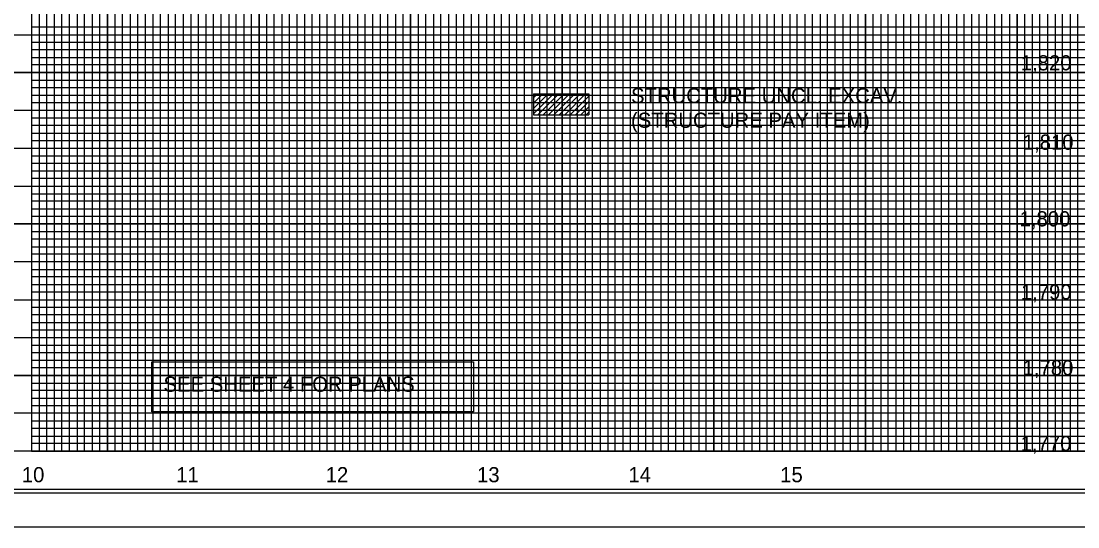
# Model space of a CAD drawing. Extents: x 572269 to 579912, y -56875 to -49627.
# Drawn here: x 573878 to 574575, y -53848 to -53514 of the extents above; entities that cross this region are included whole.
import ezdxf

# ---------------------------------------------------------------- set-up
doc = ezdxf.new("R2010")
doc.units = 0
for name, color, linetype in [('Exist Vertical Profile Horizontal Axis Label Major', 7, 'Continuous'), ('Exist Vertical Profile Vertical Axis Label', 7, 'Continuous'), ('Pattern 9', 7, 'Continuous'), ('Prop Grid Mask', 7, 'Continuous'), ('Prop PFL Text', 7, 'Continuous'), ('Sheet Cutting Line CELL', 7, 'Continuous'), ('Sheet DOT Grid CELL', 7, 'Continuous'), ('Sheet Layout Profile Border', 7, 'Continuous'), ('Sheet Plot Border Inside CELL', 7, 'Continuous'), ('Sheet Plot Border Outside CELL', 7, 'Continuous'), ('Sheet Profile CELL', 7, 'Continuous'), ('Sheet Profile Grid Major CELL', 7, 'Continuous'), ('Sheet Profile Grid Middle CELL', 7, 'Continuous'), ('Sheet Profile Grid Minor CELL', 7, 'Continuous')]:
    doc.layers.add(name, color=color, linetype=linetype)

# ---------------------------------------------------------------- blocks, each defined once
blk = doc.blocks.new('PROFILE SHEET SINGLE')
at = {"layer": 'Sheet Cutting Line CELL'}
blk.add_line((-3.34, -0.5), (30.34, -0.5), dxfattribs=at)
at = {"layer": 'Sheet DOT Grid CELL'}
for p, q in [((1, 21), (1, 0.5)), ((2, 21), (2, 0.5)), ((3, 21), (3, 0.5)), ((4, 21), (4, 0.5)), ((5, 21), (5, 0.5)), ((6, 21), (6, 0.5)), ((7, 21), (7, 0.5)), ((8, 21), (8, 0.5)), ((9, 21), (9, 0.5)), ((10, 21), (10, 0.5)), ((11, 21), (11, 0.5)), ((12, 21), (12, 0.5)), ((13, 21), (13, 0.5)), ((14, 21), (14, 0.5)), ((0, 5.5), (30, 5.5)), ((0, 4.5), (30, 4.5)), ((0, 3.5), (30, 3.5)), ((0, 2.5), (30, 2.5)), ((0, 1.5), (30, 1.5))]:
    blk.add_line(p, q, dxfattribs=at)
at = {"layer": 'Sheet Plot Border Inside CELL'}
blk.add_lwpolyline([(30.25, 21.051), (-3.08, 21.051), (-3.08, -0.051), (30.25, -0.051)], close=True, dxfattribs=at)
at = {"layer": 'Sheet Plot Border Outside CELL'}
blk.add_lwpolyline([(30.34, 21.5), (-3.34, 21.5), (-3.34, -0.5), (30.34, -0.5)], close=True, dxfattribs=at)
at = {"layer": 'Sheet Profile CELL'}
blk.add_line((30, 0.5), (0, 0.5), dxfattribs=at)
blk.add_lwpolyline([(30, 21), (0, 21), (0, 0), (30, 0)], close=True, dxfattribs=at)
at = {"layer": 'Sheet Profile Grid Major CELL'}
for points in [[(1, 21), (1, 0.5), (2, 0.5), (2, 21)], [(3, 21), (3, 0.5), (4, 0.5), (4, 21)], [(5, 21), (5, 0.5), (6, 0.5), (6, 21)], [(7, 21), (7, 0.5), (8, 0.5), (8, 21)], [(9, 21), (9, 0.5), (10, 0.5), (10, 21)], [(11, 21), (11, 0.5), (12, 0.5), (12, 21)], [(13, 21), (13, 0.5), (14, 0.5), (14, 21)], [(30, 5.5), (0, 5.5), (0, 6.5), (30, 6.5)], [(30, 3.5), (0, 3.5), (0, 4.5), (30, 4.5)], [(30, 1.5), (0, 1.5), (0, 2.5), (30, 2.5)]]:
    blk.add_lwpolyline(points, dxfattribs=at)
at = {"layer": 'Sheet Profile Grid Middle CELL'}
for points in [[(1.5, 0.5), (1.5, 21)], [(2.5, 21), (2.5, 0.5), (3.5, 0.5), (3.5, 21)], [(4.5, 21), (4.5, 0.5), (5.5, 0.5), (5.5, 21)], [(6.5, 21), (6.5, 0.5), (7.5, 0.5), (7.5, 21)], [(8.5, 21), (8.5, 0.5), (9.5, 0.5), (9.5, 21)], [(10.5, 21), (10.5, 0.5), (11.5, 0.5), (11.5, 21)], [(12.5, 21), (12.5, 0.5), (13.5, 0.5), (13.5, 21)], [(14.5, 21), (14.5, 0.5), (15.5, 0.5), (15.5, 21)], [(30, 7), (0, 7), (0, 6), (30, 6)], [(30, 5), (0, 5), (0, 4), (30, 4)], [(30, 3), (0, 3), (0, 2), (30, 2)], [(30, 1), (0, 1)]]:
    blk.add_lwpolyline(points, dxfattribs=at)
at = {"layer": 'Sheet Profile Grid Minor CELL'}
for points in [[(1.1, 21), (1.1, 0.5), (1.2, 0.5), (1.2, 21)], [(1.3, 21), (1.3, 0.5), (1.4, 0.5), (1.4, 21)], [(1.6, 21), (1.6, 0.5), (1.7, 0.5), (1.7, 21)], [(1.8, 21), (1.8, 0.5), (1.9, 0.5), (1.9, 21)], [(2.1, 21), (2.1, 0.5), (2.2, 0.5), (2.2, 21)], [(2.3, 21), (2.3, 0.5), (2.4, 0.5), (2.4, 21)], [(2.6, 21), (2.6, 0.5), (2.7, 0.5), (2.7, 21)], [(2.8, 21), (2.8, 0.5), (2.9, 0.5), (2.9, 21)], [(3.1, 21), (3.1, 0.5), (3.2, 0.5), (3.2, 21)], [(3.3, 21), (3.3, 0.5), (3.4, 0.5), (3.4, 21)], [(3.6, 21), (3.6, 0.5), (3.7, 0.5), (3.7, 21)], [(3.8, 21), (3.8, 0.5), (3.9, 0.5), (3.9, 21)], [(4.1, 21), (4.1, 0.5), (4.2, 0.5), (4.2, 21)], [(4.3, 21), (4.3, 0.5)], [(4.3, 0.5), (4.4, 0.5), (4.4, 21)], [(4.6, 21), (4.6, 0.5), (4.7, 0.5), (4.7, 21)], [(4.8, 21), (4.8, 0.5), (4.9, 0.5), (4.9, 21)], [(5.1, 21), (5.1, 0.5), (5.2, 0.5), (5.2, 21)], [(5.3, 21), (5.3, 0.5), (5.4, 0.5), (5.4, 21)], [(5.6, 21), (5.6, 0.5), (5.7, 0.5), (5.7, 21)], [(5.8, 21), (5.8, 0.5), (5.9, 0.5), (5.9, 21)], [(6.1, 21), (6.1, 0.5), (6.2, 0.5), (6.2, 21)], [(6.3, 21), (6.3, 0.5), (6.4, 0.5), (6.4, 21)], [(6.6, 21), (6.6, 0.5), (6.7, 0.5), (6.7, 21)], [(6.8, 21), (6.8, 0.5), (6.9, 0.5), (6.9, 21)], [(7.1, 21), (7.1, 0.5), (7.2, 0.5), (7.2, 21)], [(7.3, 21), (7.3, 0.5), (7.4, 0.5), (7.4, 21)], [(7.6, 21), (7.6, 0.5), (7.9, 0.5), (7.9, 21)], [(8.1, 21), (8.1, 0.5), (8.2, 0.5), (8.2, 21)], [(8.3, 21), (8.3, 0.5), (8.4, 0.5), (8.4, 21)], [(8.6, 21), (8.6, 0.5), (8.7, 0.5), (8.7, 21)], [(8.8, 21), (8.8, 0.5), (8.9, 0.5), (8.9, 21)], [(9.1, 21), (9.1, 0.5), (9.2, 0.5), (9.2, 21)], [(9.3, 21), (9.3, 0.5), (9.4, 0.5), (9.4, 21)], [(9.6, 21), (9.6, 0.5), (9.7, 0.5), (9.7, 21)], [(9.8, 21), (9.8, 0.5), (9.9, 0.5), (9.9, 21)], [(10.1, 21), (10.1, 0.5), (10.2, 0.5), (10.2, 21)], [(10.3, 21), (10.3, 0.5), (10.4, 0.5), (10.4, 21)], [(10.6, 21), (10.6, 0.5)], [(7.7, 21), (7.7, 0.5), (7.8, 0.5), (7.8, 21)], [(7.7, 20.988), (7.7, 0.5), (7.8, 0.5), (7.8, 20.988)], [(10.7, 21), (10.7, 0.5), (10.8, 0.5), (10.8, 21), (10.9, 21), (10.9, 0.5), (11.1, 0.5), (11.1, 21), (11.2, 21), (11.2, 0.5), (11.3, 0.5), (11.3, 21), (11.4, 21), (11.4, 0.5)], [(11.6, 0.5), (11.6, 21)], [(11.7, 21), (11.7, 0.5), (11.8, 0.5), (11.8, 21)], [(11.9, 21), (11.9, 0.5), (12.1, 0.5), (12.1, 21)], [(12.2, 21), (12.2, 0.5), (12.2, 0.5), (12.3, 0.5), (12.3, 21)], [(12.4, 21), (12.4, 0.5), (12.6, 0.5), (12.6, 21)], [(12.7, 21), (12.7, 0.5), (12.8, 0.5), (12.8, 21)], [(12.9, 21), (12.9, 0.5), (13.1, 0.5), (13.1, 21)], [(13.2, 21), (13.2, 0.5), (13.3, 0.5), (13.3, 21)], [(13.4, 21), (13.4, 0.5), (13.6, 0.5), (13.6, 21)], [(13.7, 21), (13.7, 0.5), (13.8, 0.5), (13.8, 21)], [(13.9, 21), (13.9, 0.5), (14.1, 0.5), (14.1, 21)], [(14.2, 21), (14.2, 0.5), (14.3, 0.5), (14.3, 21)], [(14.4, 21), (14.4, 0.5), (14.6, 0.5), (14.6, 21)], [(14.7, 21), (14.7, 0.5), (14.8, 0.5), (14.8, 21)], [(29, 6.1), (1, 6.1), (1, 5.9), (29, 5.9)], [(29, 5.8), (1, 5.8), (1, 5.7), (29, 5.7)], [(29, 5.6), (1, 5.6), (1, 5.4), (29, 5.4)], [(29, 5.3), (1, 5.3), (1, 5.2), (29, 5.2)], [(29, 5.1), (1, 5.1), (1, 4.9), (29, 4.9)], [(29, 4.8), (1, 4.8), (1, 4.7), (29, 4.7)], [(29, 4.6), (1, 4.6)], [(1, 4.4), (29, 4.4)], [(29, 4.3), (1, 4.3), (1, 4.2), (29, 4.2)], [(29, 4.1), (1, 4.1)], [(1, 3.9), (29, 3.9)], [(29, 3.8), (1, 3.8), (1, 3.7), (29, 3.7)], [(29, 3.6), (1, 3.6), (1, 3.4), (29, 3.4)], [(29, 3.3), (1, 3.3), (1, 3.2), (29, 3.2)], [(29, 3.1), (1, 3.1), (1, 2.9), (29, 2.9)], [(29, 2.8), (1, 2.8), (1, 2.7), (29, 2.7)], [(29, 2.6), (1, 2.6), (1, 2.4), (29, 2.4)], [(29, 2.3), (1, 2.3), (1, 2.2), (29, 2.2)], [(29, 2.1), (1, 2.1), (1, 1.9), (29, 1.9)], [(29, 1.8), (1, 1.8), (1, 1.7), (29, 1.7)], [(29, 1.6), (1, 1.6), (1, 1.4), (29, 1.4)], [(29, 1.3), (1, 1.3), (1, 1.2), (29, 1.2)], [(29, 1.1), (1, 1.1), (1, 0.9), (29, 0.9)], [(29, 0.8), (1, 0.8), (1, 0.7), (29, 0.7)], [(29, 0.6), (1, 0.6)]]:
    blk.add_lwpolyline(points, dxfattribs=at)

msp = doc.modelspace()

# ---------------------------------------------------------------- linework, layer by layer
at = {"layer": 'Pattern 9'}
for p, q in [((574215.64, -53575.02), (574228.87, -53561.79)), ((574215.64, -53571.48), (574225.34, -53561.79)), ((574215.64, -53567.95), (574221.8, -53561.79)), ((574215.64, -53564.41), (574218.27, -53561.79)), ((574215.64, -53561.79), (574252.14, -53561.79)), ((574215.64, -53561.79), (574215.64, -53575.6)), ((574218.6, -53575.6), (574232.41, -53561.79)), ((574222.14, -53575.6), (574235.94, -53561.79)), ((574225.67, -53575.6), (574239.48, -53561.79)), ((574229.21, -53575.6), (574243.01, -53561.79)), ((574232.75, -53575.6), (574246.34, -53562.01)), ((574236.28, -53575.6), (574250.09, -53561.79)), ((574239.82, -53575.6), (574252.13, -53563.28)), ((574252.14, -53561.79), (574252.14, -53575.6)), ((574243.35, -53575.6), (574252.13, -53566.82)), ((574246.89, -53575.6), (574252.13, -53570.35)), ((574215.64, -53575.6), (574252.14, -53575.6)), ((574250.42, -53575.6), (574252.13, -53573.89))]:
    msp.add_line(p, q, dxfattribs=at)
at = {"layer": 'Prop Grid Mask'}
msp.add_lwpolyline([(573963.96, -53738.67), (574176.21, -53738.67), (574176.21, -53771.75), (573963.96, -53771.75)], close=True, dxfattribs=at)
at = {"layer": 'Sheet Layout Profile Border'}
msp.add_lwpolyline([(573884.69, -52772.71), (573884.69, -53797.71), (575284.69, -53797.71), (575284.69, -52910.26), (575134.64, -52910.26), (575134.64, -52772.71)], close=True, dxfattribs=at)

# ---------------------------------------------------------------- block references
at = {"layer": 'Sheet Cutting Line CELL', "xscale": 50, "yscale": 50}
msp.add_blockref('PROFILE SHEET SINGLE', (573834.69, -53822.71), dxfattribs=at)

# ---------------------------------------------------------------- texts
at = {"layer": 'Exist Vertical Profile Horizontal Axis Label Major'}
for s, p in [('10', (573878.27, -53818.23)), ('11', (573980.11, -53818.23)), ('12', (574078.66, -53818.23)), ('13', (574178.49, -53818.23)), ('14', (574278.34, -53818.23)), ('15', (574378.43, -53818.23))]:
    msp.add_text(s, height=10, dxfattribs=at).set_placement(p)
at = {"layer": 'Exist Vertical Profile Vertical Axis Label'}
for s, p in [('1,820', (574537.1, -53546.27)), ('1,810', (574538.43, -53598.68)), ('1,800', (574536.31, -53649.29)), ('1,790', (574537.17, -53697.6)), ('1,780', (574538.32, -53747.6)), ('1,770', (574537.01, -53797.6))]:
    msp.add_text(s, height=10, dxfattribs=at).set_placement(p)
at = {"layer": 'Prop PFL Text'}
for s, p in [('STRUCTURE UNCL. EXCAV.', (574280.04, -53567.95)), ('(STRUCTURE PAY ITEM)', (574280.04, -53584.2)), ('SEE SHEET 4 FOR PLANS', (573971.7, -53758.5))]:
    msp.add_text(s, height=10, dxfattribs=at).set_placement(p)

doc.saveas('drawing.dxf')
